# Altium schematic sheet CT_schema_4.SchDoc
size 524 x 490 mm
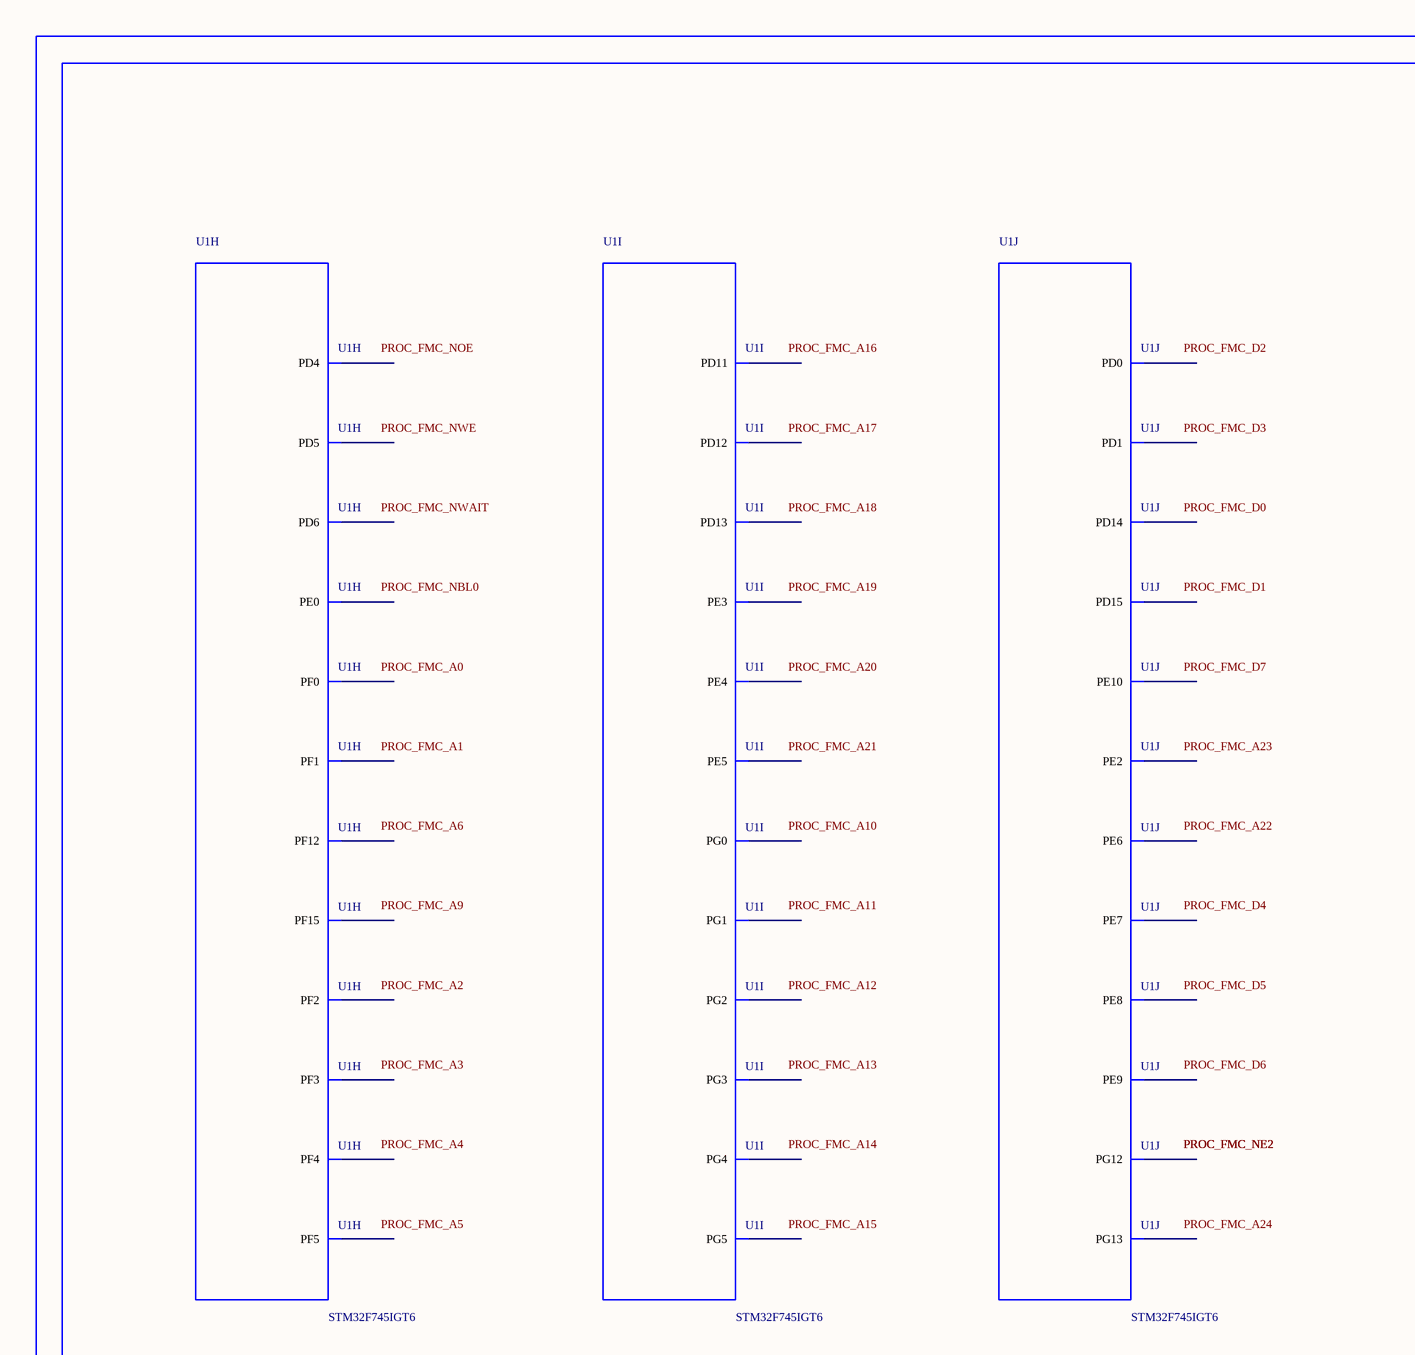
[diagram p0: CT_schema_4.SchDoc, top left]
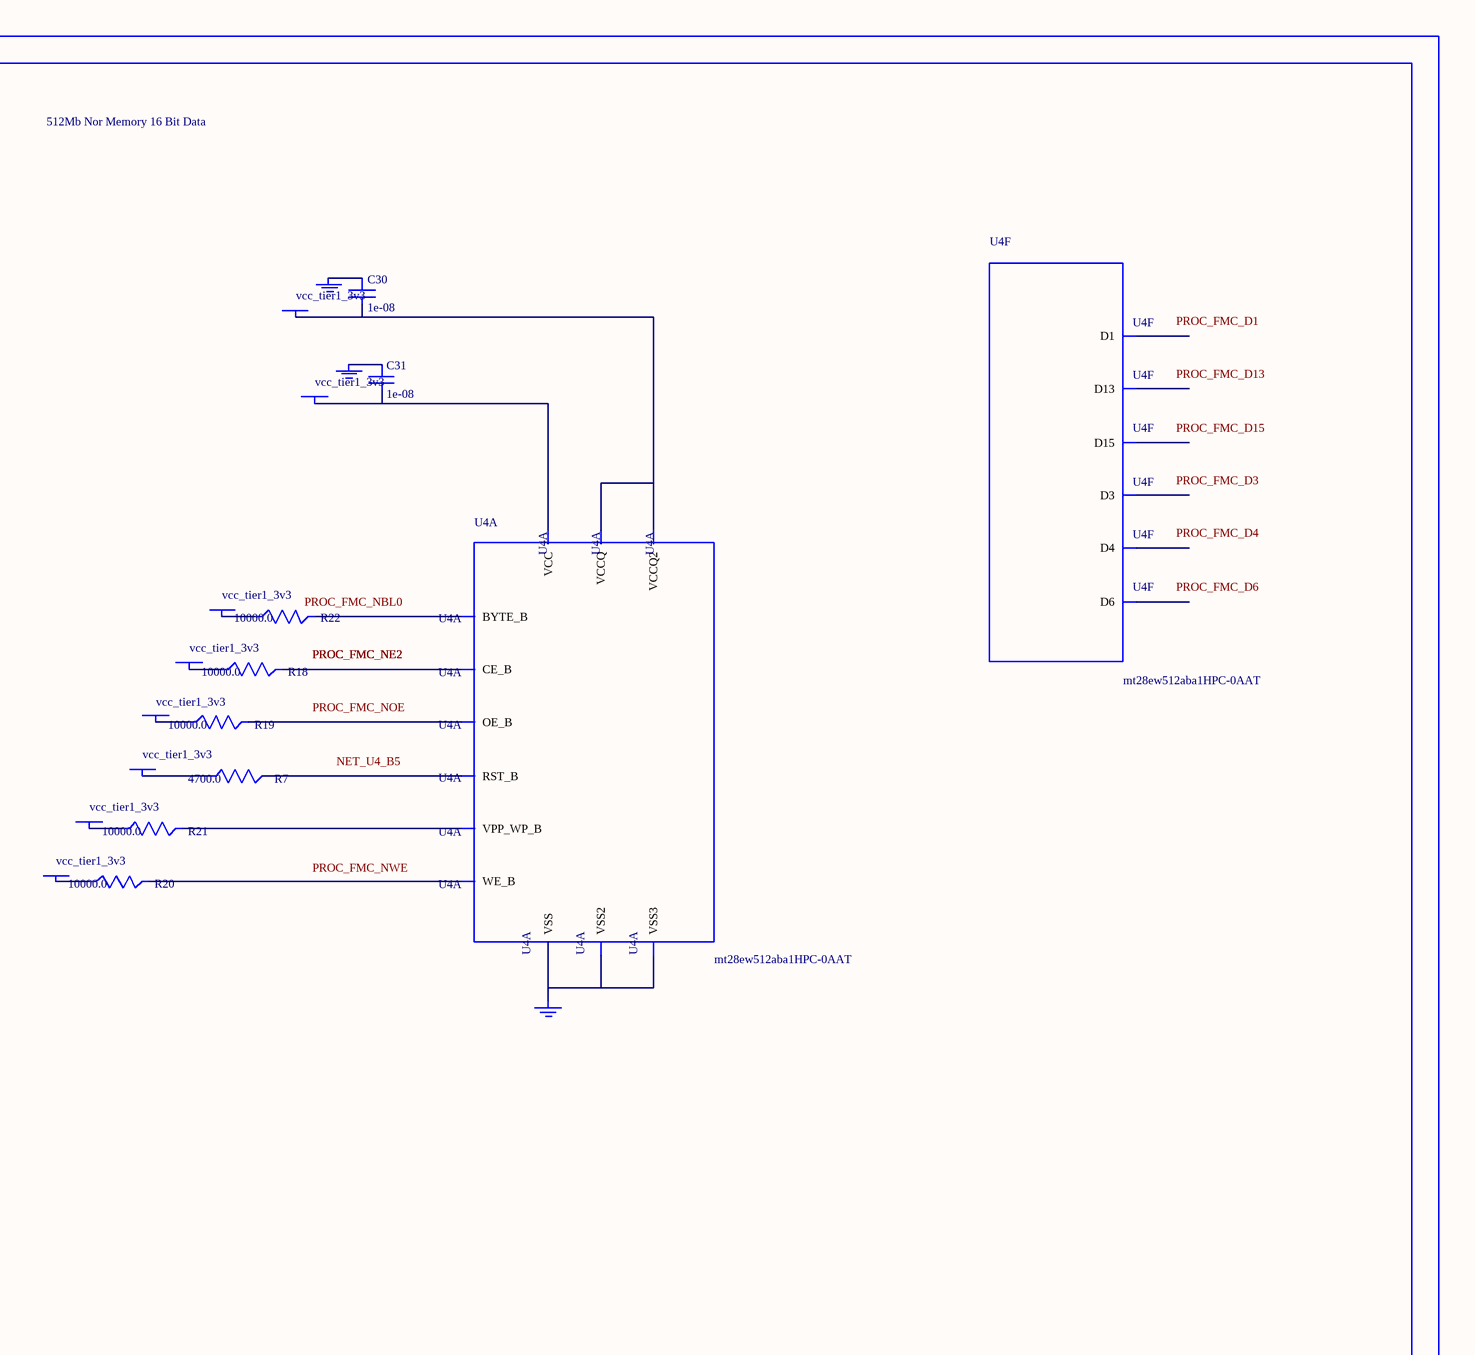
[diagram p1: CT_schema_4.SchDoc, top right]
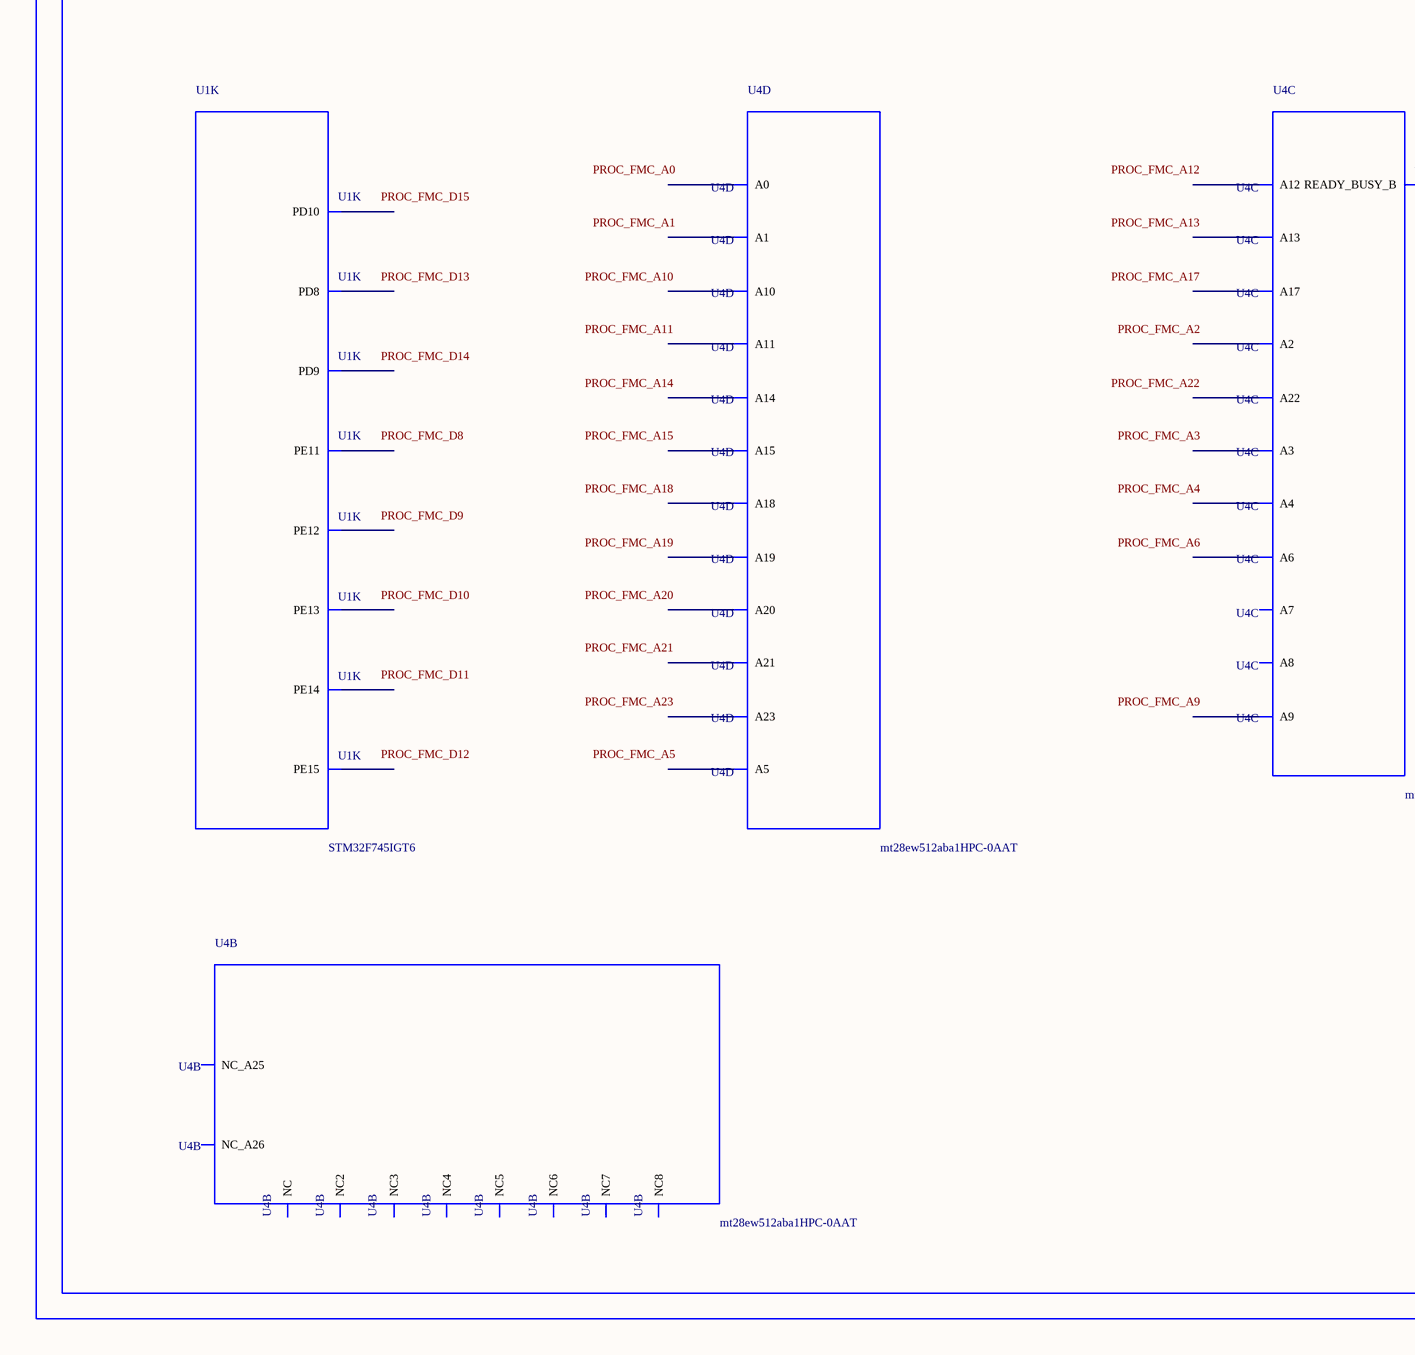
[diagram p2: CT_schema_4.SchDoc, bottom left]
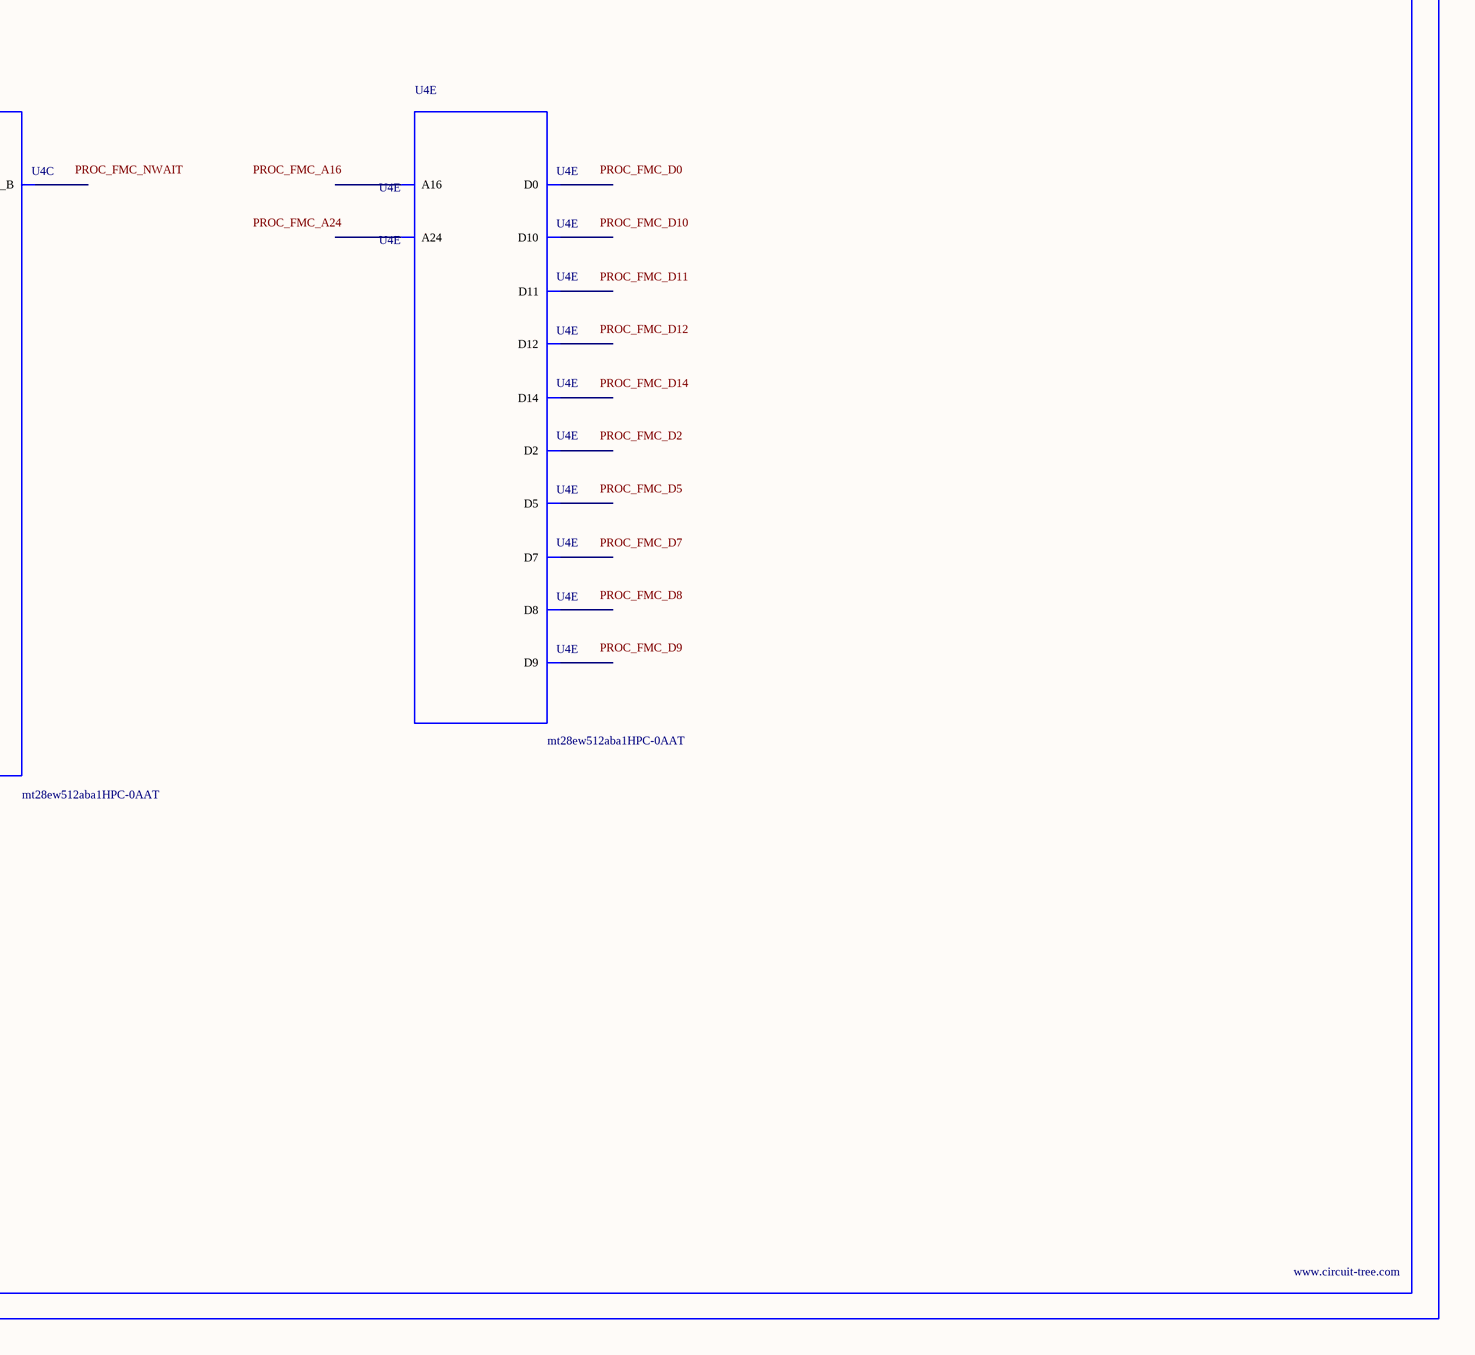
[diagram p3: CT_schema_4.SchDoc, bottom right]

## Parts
BORDER3  (no value)
C30  1e-08  [C0402]
C31  1e-08  [C0402]
GND_INSTANCE_3_0  (no value)
GND_INSTANCE_3_1  (no value)
GND_INSTANCE_3_2  (no value)
POWER_INSTANCE_3_0  vcc_tier1_3v3
POWER_INSTANCE_3_1  vcc_tier1_3v3
POWER_INSTANCE_3_2  vcc_tier1_3v3
POWER_INSTANCE_3_3  vcc_tier1_3v3
POWER_INSTANCE_3_4  vcc_tier1_3v3
POWER_INSTANCE_3_5  vcc_tier1_3v3
POWER_INSTANCE_3_6  vcc_tier1_3v3
POWER_INSTANCE_3_7  vcc_tier1_3v3
R7  4700.0  [R0603]
R18  10000.0  [R0603]
R19  10000.0  [R0603]
R20  10000.0  [R0603]
R21  10000.0  [R0603]
R22  10000.0  [R0603]
U1  STM32F745IGT6  [LQFP176]  (parts H,I,J,K of 12)
U4  mt28ew512aba1HPC-0AAT  [LBGA-64]  (parts A,B,C,D,E,F of 6)

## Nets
NetC30_1: C30.1 GND_INSTANCE_3_0.0(GND)
NetC30_2: C30.2 POWER_INSTANCE_3_0.0(PWR) U4.D8(VCCQ) U4.F1(VCCQ2)
NetC31_1: C31.1 GND_INSTANCE_3_1.0(GND)
NetC31_2: C31.2 POWER_INSTANCE_3_1.0(PWR) U4.G5(VCC)
NetGND_INSTANCE_3_2_0: GND_INSTANCE_3_2.0(GND) U4.E8(VSS) U4.H2(VSS2) U4.H7(VSS3)
NetPOWER_INSTANCE_3_2_0: POWER_INSTANCE_3_2.0(PWR) R18.1
NetPOWER_INSTANCE_3_3_0: POWER_INSTANCE_3_3.0(PWR) R19.1
NetPOWER_INSTANCE_3_4_0: POWER_INSTANCE_3_4.0(PWR) R20.1
NetPOWER_INSTANCE_3_5_0: POWER_INSTANCE_3_5.0(PWR) R21.1
NetPOWER_INSTANCE_3_6_0: POWER_INSTANCE_3_6.0(PWR) R22.1
NetPOWER_INSTANCE_3_7_0: POWER_INSTANCE_3_7.0(PWR) R7.1
NetR7_2: R7.2 U4.B5(RST_B)
NetR18_2: R18.2 U4.F2(CE_B)
NetR19_2: R19.2 U4.G2(OE_B)
NetR20_2: R20.2 U4.A5(WE_B)
NetR21_2: R21.2 U4.B4(VPP_WP_B)
NetR22_2: R22.2 U4.F7(BYTE_B)

Not connected (* = marked no-connect by the designer): U1 1(PE2) 2(PE3) 3(PE4) 4(PE5) 5(PE6) 16(PF0) 17(PF1) 18(PF2) 19(PF3) 20(PF4) 21(PF5) 60(PF12) 65(PF15) 66(PG0) 67(PG1) 68(PE7) 69(PE8) 70(PE9) 73(PE10) 74(PE11) 75(PE12) 76(PE13) 77(PE14) 78(PE15) 96(PD8) 97(PD9) 98(PD10) 99(PD11) 100(PD12) 101(PD13) 104(PD14) 105(PD15) 106(PG2) 107(PG3) 108(PG4) 109(PG5) 142(PD0) 143(PD1) 146(PD4) 147(PD5) 150(PD6) 155(PG12) 156(PG13) 169(PE0); U4 A1(NC) A2(A3) A3(A7) A4(READY_BUSY_B) A6(A9) A7(A13) A8(NC2) B1(NC_A26) B2(A4) B3(A17) B6(A8) B7(A12) B8(A22) C1(NC3) C2(A2) C3(A6) C4(A18) C5(A21) C6(A10) C7(A14) C8(A23) D1(NC4) D2(A1) D3(A5) D4(A20) D5(A19) D6(A11) D7(A15) E1(NC5) E2(A0) E3(D0) E4(D2) E5(D5) E6(D7) E7(A16) F3(D8) F4(D10) F5(D12) F6(D14) F8(A24) G1(NC6) G3(D9) G4(D11) G6(D13) G7(D15) G8(NC_A25) H1(NC7) H3(D1) H4(D3) H5(D4) H6(D6) H8(NC8)

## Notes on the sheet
- Labels drawn without touching a wire or pin: NET_U4_B5, PROC_FMC_A0, PROC_FMC_A1, PROC_FMC_A2, PROC_FMC_A3, PROC_FMC_A4, PROC_FMC_A5, PROC_FMC_A6, PROC_FMC_A9, PROC_FMC_A10, PROC_FMC_A11, PROC_FMC_A12, PROC_FMC_A13, PROC_FMC_A14, PROC_FMC_A15, PROC_FMC_A16, PROC_FMC_A17, PROC_FMC_A18, PROC_FMC_A19, PROC_FMC_A20, PROC_FMC_A21, PROC_FMC_A22, PROC_FMC_A23, PROC_FMC_A24, PROC_FMC_D0, PROC_FMC_D1, PROC_FMC_D2, PROC_FMC_D3, PROC_FMC_D4, PROC_FMC_D5, PROC_FMC_D6, PROC_FMC_D7, PROC_FMC_D8, PROC_FMC_D9, PROC_FMC_D10, PROC_FMC_D11, PROC_FMC_D12, PROC_FMC_D13, PROC_FMC_D14, PROC_FMC_D15, PROC_FMC_NBL0, PROC_FMC_NOE, PROC_FMC_NWAIT, PROC_FMC_NWE

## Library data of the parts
BORDER3 = BORDER_PAGE3
C30 C31 = C0402C103K3RAC
GND_INSTANCE_3_0-GND_INSTANCE_3_2 = GND
POWER_INSTANCE_3_0-POWER_INSTANCE_3_7 = PWR
R7 = RC0603JR-074K7L
R18-R22 = RC0603JR-0710KL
